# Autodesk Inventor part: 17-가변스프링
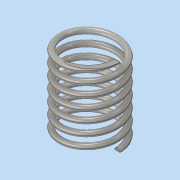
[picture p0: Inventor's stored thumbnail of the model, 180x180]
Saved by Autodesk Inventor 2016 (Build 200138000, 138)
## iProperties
Created: 2020-01
Part Number: 17-가변스프링
Material: 스테인레스 스틸
Document SubType Name: Modeling
Designer: MIRAE
Density: 8 g/cm^3
Appearance: 반연마
Mass: 10.8787 g
Surface Area: 27.5607 cm^2
Volume: 1.35984 cm^3
Author: MIRAE
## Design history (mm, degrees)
sketch "스케치1"
  geometry: L1 (0, 0)-(10, 0); L2 (10, 0)-(10, 28.7); L3 (10, 28.7)-(0, 28.7); L4 (0, 28.7)-(0, 0); C1 r 1 at (10, 0)
  constraints: 8 end point, 2 parallel, 1 centre point, 1 coincident, 1 horizontal, 1 perpendicular
  dimensions: "d0" = 2 diameter of C1; "d1" = 20 diameter of L2 L4; "d3" = 28.7 distance of L1.end L2.end (derived)
feature "코일1" sketch "스케치1" pitch "d4" = 25.4; turns "d6" = 7; dims "d5" = 28.7 (= d3), "d7" = 0, angle "d8" = 90 deg, angle "d9" = 90 deg, "d10" = 0, "d11" = 0
sketch "스케치2"
  geometry: L1 (-11, 0)-(-9, 0) reference; 1 further point
  constraints: 1 horizontal alignment
extrude "돌출1" cut sketch "스케치2" distance "d12" = 10; taper "d13" = 0 deg
node "작업 평면1"
sketch "스케치3"
  geometry: L1 (1, 0)-(-1, 0) reference; 1 further point
  constraints: 1 horizontal alignment
extrude "돌출2" cut sketch "스케치3" stored distance "d15" = 10; taper "d16" = 0 deg
node "솔리드1"
node "절단 모서리 투영1"
node "절단 모서리 투영2"
other parameters: "d14" = 90 deg
